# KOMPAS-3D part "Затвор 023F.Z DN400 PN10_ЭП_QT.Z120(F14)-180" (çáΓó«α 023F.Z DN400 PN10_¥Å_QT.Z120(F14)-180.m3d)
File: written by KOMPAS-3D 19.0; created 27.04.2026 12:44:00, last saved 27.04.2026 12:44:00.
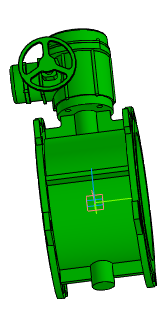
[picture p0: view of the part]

Document properties: Полное имя файла: Затвор 023F.Z DN400 PN10 + электропривод QT.Z120(F14)-180.a3d

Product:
- Part/product: Затвор 023F.Z DN400 PN10_ЭП_QT.Z120(F14)-180
    Масса: 220.188
  - Body: Тело 1
      Масса: 220.701

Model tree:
1. Операция без истории:1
